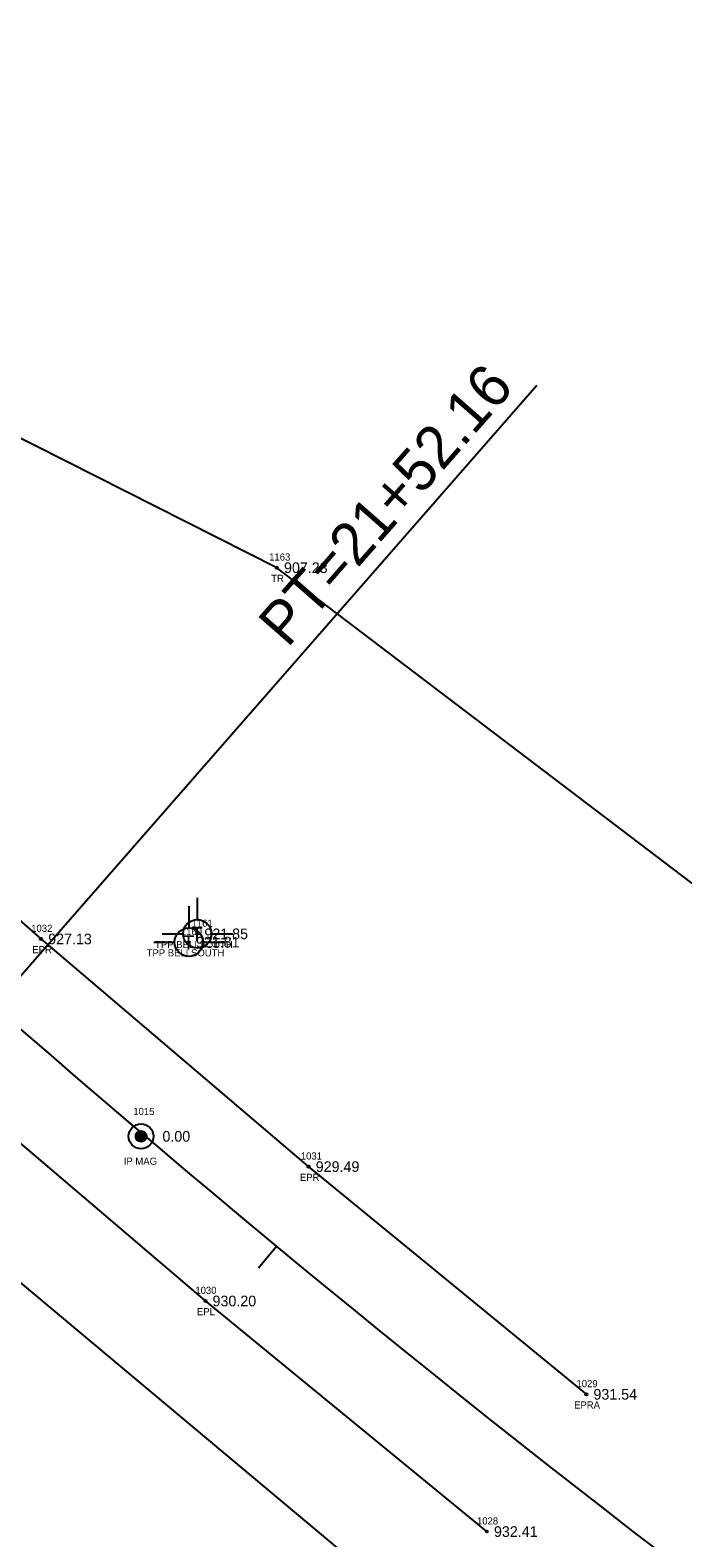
# Model space of a CAD drawing. Extents: x 1393163 to 1398407, y 1072670 to 1074651.
# Drawn here: x 1397048.8 to 1397140.6, y 1074054.9 to 1074266.9 of the extents above; entities that cross this region are included whole.
import ezdxf

# ---------------------------------------------------------------- set-up
doc = ezdxf.new("R2010")
doc.units = 0
for name, color, linetype in [('RD_EX_DV_Prop_txCode', 7, 'Continuous'), ('RD_EX_DV_PropPin', 7, 'Continuous'), ('RD_EX_Road', 7, 'Continuous'), ('RD_EX_Road_txCode', 7, 'Continuous'), ('RD_EX_TX_DV_Prop_ELEV', 7, 'Continuous'), ('RD_EX_TX_Road_ELEV', 7, 'Continuous'), ('RD_EX_TX_UT_ELEV', 7, 'Continuous'), ('RD_EX_TX_VEG_ELEV', 7, 'Continuous'), ('RD_EX_UT', 7, 'Continuous'), ('RD_EX_UT_txCode', 7, 'Continuous'), ('RD_EX_VEG', 7, 'Continuous'), ('RD_EX_VEG_txCode', 7, 'Continuous'), ('RD_HC_Cl', 7, 'Continuous'), ('RD_HC_Data', 7, 'Continuous'), ('RD_HC_Data_Tic', 7, 'Continuous'), ('RD_SMD_Locator', 7, 'Continuous')]:
    doc.layers.add(name, color=color, linetype=linetype)

msp = doc.modelspace()

# ---------------------------------------------------------------- linework, layer by layer
at = {"layer": 'RD_EX_DV_PropPin'}
for p, q in [((1397063.98, 1074110.72), (1397063.98, 1074111.99)), ((1397064.02, 1074110.7), (1397064.02, 1074112.01)), ((1397064.05, 1074110.68), (1397064.05, 1074112.03)), ((1397064.09, 1074110.66), (1397064.09, 1074112.04)), ((1397064.12, 1074110.64), (1397064.12, 1074112.06)), ((1397064.16, 1074110.63), (1397064.16, 1074112.07)), ((1397064.19, 1074110.62), (1397064.19, 1074112.08)), ((1397064.23, 1074110.61), (1397064.23, 1074112.09)), ((1397064.26, 1074110.6), (1397064.26, 1074112.1)), ((1397064.3, 1074110.6), (1397064.3, 1074112.11)), ((1397064.33, 1074110.59), (1397064.33, 1074112.11)), ((1397064.37, 1074110.59), (1397064.37, 1074112.11)), ((1397064.4, 1074110.59), (1397064.4, 1074112.11)), ((1397064.44, 1074110.59), (1397064.44, 1074112.11)), ((1397064.47, 1074110.59), (1397064.47, 1074112.11)), ((1397064.51, 1074110.6), (1397064.51, 1074112.11)), ((1397064.54, 1074110.6), (1397064.54, 1074112.1)), ((1397064.58, 1074110.61), (1397064.58, 1074112.09)), ((1397064.61, 1074110.62), (1397064.61, 1074112.08)), ((1397064.65, 1074110.63), (1397064.65, 1074112.07)), ((1397064.68, 1074110.64), (1397064.68, 1074112.06)), ((1397064.72, 1074110.66), (1397064.72, 1074112.04)), ((1397064.76, 1074110.68), (1397064.76, 1074112.03)), ((1397064.79, 1074110.7), (1397064.79, 1074112.01)), ((1397064.83, 1074110.72), (1397064.83, 1074111.99)), ((1397063.67, 1074111.16), (1397063.67, 1074111.55)), ((1397063.7, 1074111.05), (1397063.7, 1074111.65)), ((1397063.74, 1074110.98), (1397063.74, 1074111.72)), ((1397063.77, 1074110.93), (1397063.77, 1074111.78)), ((1397063.81, 1074110.88), (1397063.81, 1074111.83)), ((1397063.84, 1074110.84), (1397063.84, 1074111.87)), ((1397063.88, 1074110.8), (1397063.88, 1074111.9)), ((1397063.91, 1074110.77), (1397063.91, 1074111.93)), ((1397063.95, 1074110.74), (1397063.95, 1074111.96)), ((1397064.86, 1074110.74), (1397064.86, 1074111.96)), ((1397064.9, 1074110.77), (1397064.9, 1074111.93)), ((1397064.93, 1074110.8), (1397064.93, 1074111.9)), ((1397064.97, 1074110.84), (1397064.97, 1074111.87)), ((1397065, 1074110.88), (1397065, 1074111.83)), ((1397065.04, 1074110.93), (1397065.04, 1074111.78)), ((1397065.07, 1074110.98), (1397065.07, 1074111.72)), ((1397065.11, 1074111.05), (1397065.11, 1074111.65)), ((1397065.14, 1074111.16), (1397065.14, 1074111.55))]:
    msp.add_line(p, q, dxfattribs=at)
for radius in [1.75, 0.761]:
    msp.add_circle((1397064.4, 1074111.35), radius, dxfattribs=at)
at = {"layer": 'RD_EX_Road'}
for points in [[(1397127.02, 1074075.08), (1397087.96, 1074107.09), (1397050.33, 1074139.1), (1397012.08, 1074172.65), (1396975.18, 1074205.06), (1396938.56, 1074237.05), (1396899.33, 1074270.29), (1396859.1, 1074302.06), (1396826.71, 1074324.07), (1396788.75, 1074345.97), (1396771.6, 1074353.88), (1396724.53, 1074372.71), (1396674.59, 1074386.64), (1396624.89, 1074395.26)], [(1397113.03, 1074055.78), (1397073.45, 1074088.2), (1397033.12, 1074122.53), (1397005.07, 1074146.99), (1396959.64, 1074187.05), (1396921.5, 1074220.1), (1396884.1, 1074252.26), (1396844.62, 1074282.93), (1396805.23, 1074308.91), (1396761.89, 1074332.05), (1396716.72, 1074350.46), (1396669.99, 1074363.58), (1396621.68, 1074371.65)]]:
    msp.add_lwpolyline(points, dxfattribs=at)
at = {"layer": 'RD_EX_UT'}
for p, q in [((1397072.3, 1074144.89), (1397072.3, 1074141.82)), ((1397071.11, 1074143.72), (1397071.11, 1074140.65)), ((1397067.37, 1074139.84), (1397070.3, 1074139.84)), ((1397074.3, 1074139.84), (1397077.37, 1074139.84)), ((1397066.18, 1074138.67), (1397069.11, 1074138.67)), ((1397073.11, 1074138.67), (1397076.18, 1074138.67))]:
    msp.add_line(p, q, dxfattribs=at)
for centre in [(1397072.3, 1074139.82), (1397071.11, 1074138.65)]:
    msp.add_circle(centre, 2, dxfattribs=at)
at = {"layer": 'RD_EX_VEG'}
for points in [[(1397153.93, 1074137.81), (1397083.5, 1074191.3), (1396998.48, 1074234.23), (1396876.65, 1074321.33), (1396895.14, 1074321.61), (1397002.52, 1074272.66), (1397029.25, 1074267.76)], [(1397102.45, 1074044.8), (1397023.2, 1074111.05), (1396958.86, 1074125.87), (1396923.23, 1074126.87), (1396893.89, 1074108.8)]]:
    msp.add_lwpolyline(points, dxfattribs=at)
at = {"layer": 'RD_HC_Cl'}
msp.add_arc((1398300.81, 1075567), 1909.5, 228.82706, 238.54375, dxfattribs=at)
at = {"layer": 'RD_HC_Data'}
msp.add_line((1397043.72, 1074129.67), (1397120.06, 1074216.96), dxfattribs=at)
at = {"layer": 'RD_HC_Data_Tic'}
msp.add_line((1397083.44, 1074095.88), (1397080.89, 1074092.8), dxfattribs=at)
at = {"layer": 'RD_SMD_Locator'}
for centre in [(1397083.5, 1074191.3), (1397072.3, 1074139.82), (1397050.33, 1074139.1), (1397071.11, 1074138.65), (1397064.4, 1074111.35), (1397087.96, 1074107.09), (1397073.45, 1074088.2), (1397127.02, 1074075.08), (1397113.03, 1074055.78)]:
    msp.add_circle(centre, 0.15, dxfattribs=at)

# ---------------------------------------------------------------- texts
at = {"layer": 'RD_EX_DV_Prop_txCode'}
for s, p in [('1015', (1397063.3, 1074114.35)), ('IP MAG', (1397061.96, 1074107.35))]:
    msp.add_text(s, height=1, dxfattribs=at).set_placement(p)
at = {"layer": 'RD_EX_Road_txCode'}
for s, p in [('1032', (1397048.94, 1074140.1)), ('EPR', (1397049.1, 1074137.1)), ('1031', (1397086.86, 1074108.09)), ('EPR', (1397086.73, 1074105.09)), ('1030', (1397072.03, 1074089.2)), ('EPL', (1397072.25, 1074086.2)), ('1029', (1397125.63, 1074076.08)), ('EPRA', (1397125.3, 1074073.08)), ('1028', (1397111.64, 1074056.78))]:
    msp.add_text(s, height=1, dxfattribs=at).set_placement(p)
at = {"layer": 'RD_EX_TX_DV_Prop_ELEV'}
msp.add_text('0.00', height=1.5, dxfattribs=at).set_placement((1397067.4, 1074110.6))
at = {"layer": 'RD_EX_TX_Road_ELEV'}
for s, p in [('927.13', (1397051.33, 1074138.35)), ('929.49', (1397088.96, 1074106.34)), ('930.20', (1397074.45, 1074087.45)), ('931.54', (1397128.02, 1074074.33)), ('932.41', (1397114.03, 1074055.03))]:
    msp.add_text(s, height=1.5, dxfattribs=at).set_placement(p)
at = {"layer": 'RD_EX_TX_UT_ELEV'}
for s, p in [('921.85', (1397073.3, 1074139.07)), ('921.81', (1397072.11, 1074137.9))]:
    msp.add_text(s, height=1.5, dxfattribs=at).set_placement(p)
at = {"layer": 'RD_EX_TX_VEG_ELEV'}
msp.add_text('907.23', height=1.5, dxfattribs=at).set_placement((1397084.5, 1074190.55))
at = {"layer": 'RD_EX_UT'}
for p in [(1397070.26, 1074137.6), (1397071.45, 1074138.78)]:
    msp.add_text('T', height=2, dxfattribs=at).set_placement(p)
at = {"layer": 'RD_EX_UT_txCode'}
for s, p in [('1161', (1397071.5, 1074140.82)), ('1160', (1397069.99, 1074139.65)), ('TPP BELLSOUTH', (1397065.18, 1074136.65)), ('TPP BELLSOUTH', (1397066.36, 1074137.82))]:
    msp.add_text(s, height=1, dxfattribs=at).set_placement(p)
at = {"layer": 'RD_EX_VEG_txCode'}
for s, p in [('1163', (1397082.41, 1074192.3)), ('TR', (1397082.7, 1074189.3))]:
    msp.add_text(s, height=1, dxfattribs=at).set_placement(p)
at = {"layer": 'RD_HC_Data'}
msp.add_text('PT=21+52.16', height=6, rotation=48.8271, dxfattribs=at).set_placement((1397085, 1074179.92))

doc.saveas('drawing.dxf')
